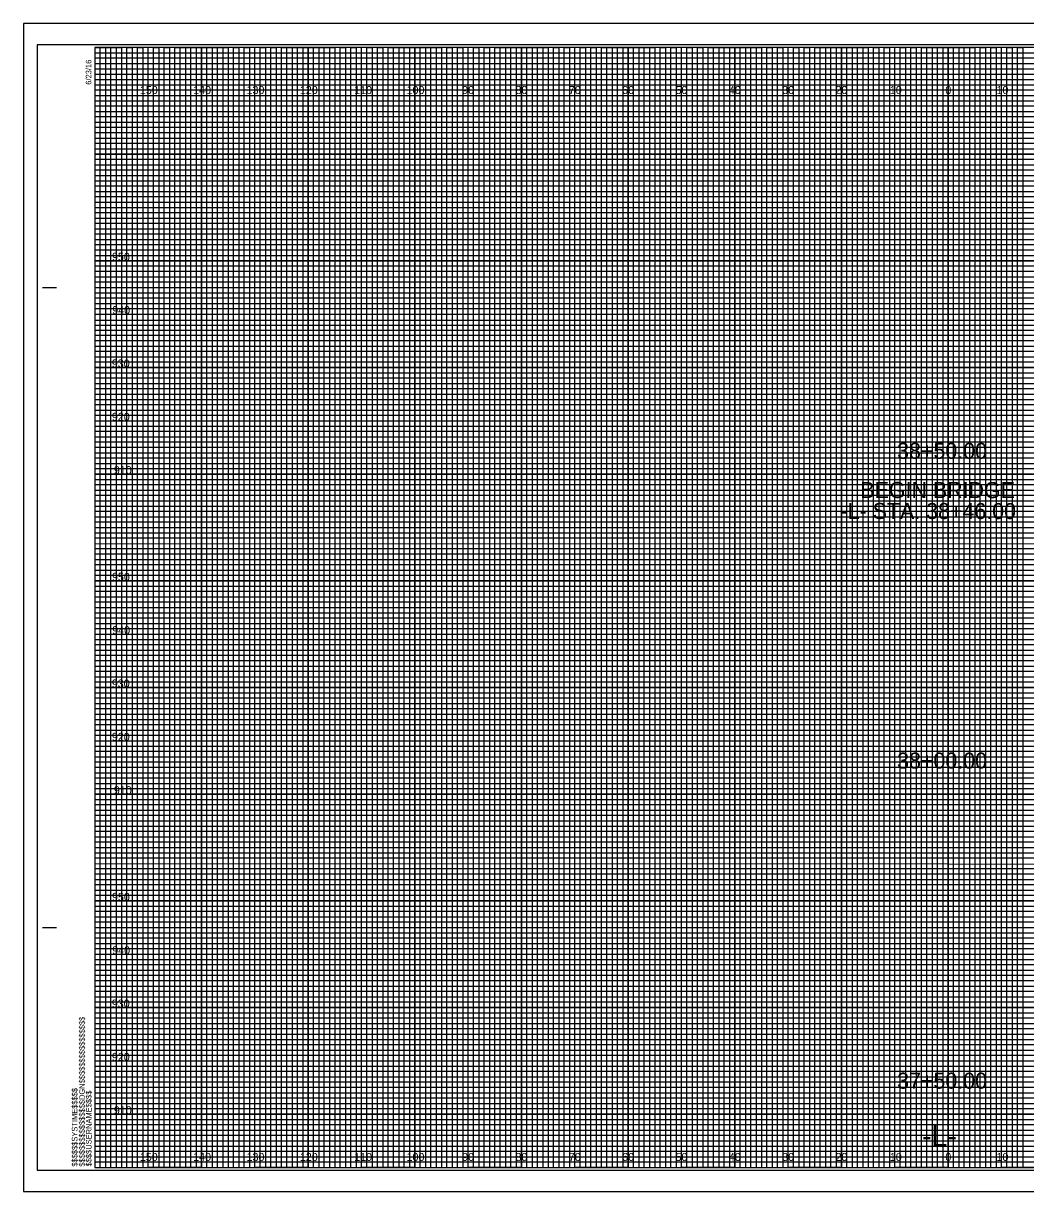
# Model space of a CAD drawing. Extents: x -13 to 323, y -4 to 3074.
# Drawn here: x -13.4 to 174.5, y 1095.5 to 1314.5 of the extents above; entities that cross this region are included whole.
import ezdxf

# ---------------------------------------------------------------- set-up
doc = ezdxf.new("R2010")
doc.units = 0
for name, color, linetype in [('Prop XS Alignment Label', 7, 'Continuous'), ('Prop XS Elevation Labels', 7, 'Continuous'), ('Prop XS Offset Labels', 7, 'Continuous'), ('Prop XS SE Text', 7, 'Continuous'), ('Prop XS Station Labels', 7, 'Continuous'), ('Sheet Cross Section CELL', 7, 'Continuous'), ('Sheet Cross Section Grid Major CELL', 7, 'Continuous'), ('Sheet Cross Section Grid Middle CELL', 7, 'Continuous'), ('Sheet Cross Section Grid Minor 1 CELL', 7, 'Continuous'), ('Sheet Cross Section Grid Minor 2 CELL', 7, 'Continuous'), ('Sheet Cutting Line CELL', 7, 'Continuous'), ('Sheet DOT Grid CELL', 7, 'Continuous'), ('Sheet Plot Border Inside CELL', 7, 'Continuous'), ('Sheet Plot Border Outside CELL', 7, 'Continuous')]:
    doc.layers.add(name, color=color, linetype=linetype)

msp = doc.modelspace()

# ---------------------------------------------------------------- linework, layer by layer
at = {"layer": 'Sheet Cross Section CELL'}
for p, q in [((-9.8, 1265), (-7.3, 1265)), ((-9.7, 1265), (-7.2, 1265)), ((-9.8, 1145), (-7.3, 1145)), ((-9.7, 1145), (-7.2, 1145)), ((0, 1100), (0, 1100)), ((0, 1100), (0, 1100)), ((0, 1100), (0, 1100)), ((0, 1100), (0, 1100)), ((0, 1100), (0, 1100)), ((0, 1100), (0, 1100)), ((0, 1100), (0, 1100))]:
    msp.add_line(p, q, dxfattribs=at)
msp.add_lwpolyline([(320, 1310), (0, 1310), (0, 1100), (320, 1100)], close=True, dxfattribs=at)
at = {"layer": 'Sheet Cross Section Grid Major CELL'}
for p, q in [((10, 1310), (0, 1310)), ((10, 1100), (10, 1310)), ((30, 1310), (20, 1310)), ((20, 1310), (20, 1100)), ((30, 1100), (30, 1310)), ((50, 1310), (40, 1310)), ((40, 1310), (40, 1100)), ((50, 1100), (50, 1310)), ((70, 1310), (60, 1310)), ((60, 1310), (60, 1100)), ((70, 1100), (70, 1310)), ((90, 1310), (80, 1310)), ((80, 1310), (80, 1100)), ((90, 1100), (90, 1310)), ((110, 1310), (100, 1310)), ((100, 1310), (100, 1100)), ((110, 1100), (110, 1310)), ((130, 1310), (120, 1310)), ((120, 1310), (120, 1100)), ((130, 1100), (130, 1310)), ((150, 1310), (140, 1310)), ((140, 1310), (140, 1100)), ((150, 1100), (150, 1310)), ((170, 1310), (160, 1310)), ((160, 1310), (160, 1100)), ((170, 1100), (170, 1310)), ((20, 1100), (10, 1100)), ((40, 1100), (30, 1100)), ((60, 1100), (50, 1100)), ((80, 1100), (70, 1100)), ((100, 1100), (90, 1100)), ((120, 1100), (110, 1100)), ((140, 1100), (130, 1100)), ((160, 1100), (150, 1100)), ((180, 1100), (170, 1100))]:
    msp.add_line(p, q, dxfattribs=at)
for points in [[(0, 1300), (320, 1300), (320, 1290), (0, 1290)], [(0, 1280), (320, 1280), (320, 1270), (0, 1270)], [(0, 1260), (320, 1260), (320, 1250), (0, 1250)], [(0, 1240), (320, 1240), (320, 1230), (0, 1230)], [(0, 1220), (320, 1220), (320, 1210), (0, 1210)], [(0, 1200), (320, 1200), (320, 1190), (0, 1190)], [(0, 1180), (320, 1180), (320, 1170), (0, 1170)], [(0, 1160), (320, 1160), (320, 1150), (0, 1150)], [(0, 1140), (320, 1140), (320, 1130), (0, 1130)], [(0, 1120), (320, 1120), (320, 1110), (0, 1110)]]:
    msp.add_lwpolyline(points, dxfattribs=at)
at = {"layer": 'Sheet Cross Section Grid Middle CELL'}
for points in [[(0, 1310), (5, 1310), (5, 1100), (15, 1100), (15, 1310), (25, 1310), (25, 1100), (35, 1100), (35, 1310), (45, 1310), (45, 1100), (55, 1100), (55, 1310), (65, 1310), (65, 1100), (75, 1100), (75, 1310), (85, 1310), (85, 1100), (95, 1100), (95, 1310), (105, 1310), (105, 1100), (115, 1100), (115, 1310), (125, 1310), (125, 1100), (135, 1100), (135, 1310), (145, 1310), (145, 1100), (155, 1100), (155, 1310), (165, 1310), (165, 1100), (175, 1100)], [(0, 1305), (275, 1305)], [(0, 1285), (320, 1285), (320, 1295), (0, 1295)], [(0, 1265), (320, 1265), (320, 1275), (0, 1275)], [(0, 1245), (320, 1245), (320, 1255), (0, 1255)], [(0, 1225), (320, 1225), (320, 1235), (0, 1235)], [(0, 1205), (320, 1205), (320, 1215), (0, 1215)], [(0, 1185), (320, 1185), (320, 1195), (0, 1195)], [(0, 1165), (320, 1165), (320, 1175), (0, 1175)], [(0, 1145), (320, 1145), (320, 1155), (0, 1155)], [(0, 1125), (320, 1125), (320, 1135), (0, 1135)], [(0, 1105), (320, 1105), (320, 1115), (0, 1115)]]:
    msp.add_lwpolyline(points, dxfattribs=at)
at = {"layer": 'Sheet Cross Section Grid Minor 1 CELL'}
for p, q in [((0, 1309), (260, 1309)), ((260, 1307.98), (0, 1307.98)), ((0, 1307.98), (0, 1307)), ((0, 1307), (260, 1307)), ((260, 1305.89), (0, 1305.89)), ((0, 1305.89), (0, 1304)), ((0, 1304), (320, 1304))]:
    msp.add_line(p, q, dxfattribs=at)
for points in [[(0, 1303), (270, 1303), (320, 1303), (320, 1302), (0, 1302)], [(0, 1301), (320, 1301), (320, 1299), (0, 1299)], [(0, 1298), (320, 1298), (320, 1297), (0, 1296.98)], [(0, 1296), (320, 1296), (320, 1294), (0, 1294)], [(0, 1293), (320, 1293), (320, 1292), (0, 1292)], [(0, 1291), (320, 1291), (320, 1289), (0, 1289)], [(0, 1288), (320, 1288), (320, 1287), (0, 1287)], [(0, 1286), (320, 1286), (320, 1284), (0, 1284)], [(0, 1283), (320, 1283), (320, 1282), (0, 1282)], [(0, 1281), (320, 1281), (320, 1279), (0, 1279)], [(0, 1278), (320, 1278), (320, 1277), (0, 1277)], [(0, 1276), (320, 1276), (320, 1273.95), (320, 1273), (320, 1272), (0, 1272)], [(0, 1274), (320, 1274), (320, 1273), (0, 1273)], [(0, 1271), (320, 1271), (320, 1269), (0, 1269.03)], [(0, 1269.03), (320, 1269), (320, 1268), (0, 1268)], [(0, 1267), (320, 1267), (320, 1266), (0, 1266)], [(0, 1264), (320, 1264), (320, 1263), (0, 1263)], [(0, 1262), (320, 1262), (320, 1261), (0, 1261)], [(-0.07, 1258.89), (320, 1258.89), (320, 1257.88), (-0.07, 1257.88)], [(0, 1257), (320, 1257), (320, 1256), (0, 1256)], [(0, 1254), (320, 1254), (320, 1253), (0, 1253)], [(0, 1252), (320, 1252), (320, 1251), (0, 1251)], [(0, 1249), (320, 1249), (320, 1248), (0, 1248)], [(0, 1247), (320, 1247), (320, 1246), (0, 1246)], [(0, 1244), (320, 1244), (320, 1243), (0, 1243)], [(0, 1242), (320, 1242), (320, 1241), (0, 1241)], [(0, 1239), (320, 1239), (319.99, 1237.98), (0, 1238)], [(0, 1237), (320, 1237), (320, 1236), (0, 1236)], [(0, 1234), (320, 1234), (320, 1233), (0, 1233)], [(0, 1232), (320, 1232), (320, 1231), (0, 1231)], [(0, 1229), (320, 1229), (320, 1228), (0, 1228)], [(0, 1227), (320, 1227), (320, 1226), (0, 1226)], [(0, 1224), (320, 1224), (320, 1223), (0, 1223)], [(0, 1222), (320, 1222), (320, 1221), (0, 1221)], [(0, 1219), (320, 1219), (320, 1218), (0, 1218)], [(0, 1216.99), (320.07, 1216.91), (320, 1216), (0, 1216)], [(0, 1214), (320, 1214), (320, 1213), (0, 1213)], [(0, 1212), (320, 1212), (320, 1211), (0, 1211)], [(0, 1209), (320, 1209), (320, 1208), (0, 1208)], [(0, 1207), (320, 1207), (320, 1206), (0, 1206)], [(0, 1204), (320, 1204), (320, 1203), (0, 1203)], [(0, 1202), (320, 1202), (320, 1201), (0, 1201)], [(0, 1199), (320, 1199), (320, 1198), (0, 1198)], [(0, 1197), (320, 1197), (320, 1196), (0, 1196)], [(0, 1194), (320, 1194), (320, 1193), (0, 1193)], [(0, 1192), (320, 1192), (320, 1191), (0, 1191)], [(0, 1189), (320, 1189), (320, 1188), (0, 1188)], [(0, 1187), (320, 1187), (320, 1186), (0, 1186)], [(0, 1184), (320, 1184), (320, 1183), (0, 1183)], [(0, 1182), (320, 1182), (320, 1181), (0, 1181)], [(0, 1179), (320, 1179), (319.99, 1177.98), (0, 1178)], [(0, 1177), (320, 1177), (320, 1176), (0, 1176)], [(0, 1174), (320, 1174), (320, 1173), (0, 1173)], [(0, 1172), (320, 1172), (320, 1171), (0, 1171)], [(0, 1169), (320, 1169), (320, 1168), (0, 1168)], [(0, 1167), (320, 1167), (320, 1166), (0, 1166)], [(0, 1164), (320, 1164), (320, 1163), (0, 1163)], [(0, 1162), (320, 1162), (320, 1161), (0, 1161)], [(0, 1159), (320, 1159), (320, 1158), (0, 1158)], [(0, 1156.99), (320.07, 1156.91), (320, 1156), (0, 1156)], [(0, 1154), (320, 1154), (320, 1153), (0, 1153)], [(0, 1152), (320, 1152), (320, 1151), (0, 1151)], [(0, 1149), (320, 1149), (320, 1148), (0, 1148)], [(0, 1147), (320, 1147), (320, 1146), (0, 1146)], [(0, 1144), (320, 1144), (320, 1143), (0, 1143)], [(0, 1142), (320, 1142), (320, 1141), (0, 1141)], [(0, 1139), (320, 1139), (320, 1138), (0, 1138)], [(0, 1137), (320, 1137), (320, 1136), (0, 1136)], [(0, 1134), (320, 1134), (320, 1133), (0, 1133)], [(0, 1132), (320, 1132), (320, 1131), (0, 1131)], [(0, 1129), (320, 1129), (320, 1128), (0, 1128)], [(0, 1127), (320, 1127), (320, 1126), (0, 1126)], [(0, 1124), (320, 1124), (320, 1123), (0, 1123)], [(0, 1122), (320, 1122), (320, 1121), (0, 1121)], [(0, 1119), (320, 1119), (320, 1118), (0, 1118)], [(0, 1117), (320, 1117), (320, 1116), (0, 1116)], [(0, 1114), (320, 1114), (320, 1113), (0, 1113)], [(0, 1112), (320, 1112), (320, 1111), (0, 1111)], [(0, 1109), (320, 1109), (320, 1108), (0, 1108)], [(0, 1107), (320, 1107), (320, 1106), (0, 1106)], [(0, 1104), (320, 1104), (320, 1103), (0, 1103)], [(0, 1102), (320, 1102), (320, 1101), (0, 1101)]]:
    msp.add_lwpolyline(points, dxfattribs=at)
at = {"layer": 'Sheet Cross Section Grid Minor 2 CELL'}
for points in [[(0, 1100), (1, 1100), (1, 1310), (2, 1310), (2, 1100)], [(2, 1100), (3, 1100), (3, 1310), (4, 1310), (4, 1100)], [(5, 1100), (6, 1100), (6, 1310), (7, 1310), (7, 1100)], [(7, 1100), (8, 1100), (8, 1310), (9, 1310), (9, 1100)], [(10, 1100), (11, 1100), (11, 1310), (12, 1310), (12, 1100)], [(12, 1100), (13, 1100), (13, 1310), (14, 1310), (14, 1100)], [(15, 1100), (16, 1100), (16, 1310), (17, 1310), (17, 1100)], [(17, 1100), (18, 1100), (18, 1310), (19, 1310), (19, 1100)], [(20, 1100), (21, 1100), (21, 1310), (22, 1310), (22, 1100)], [(22, 1100), (23, 1100), (23, 1310), (24, 1310), (24, 1100)], [(25, 1100), (26, 1100), (26, 1310), (27, 1310), (27, 1100)], [(27, 1100), (28, 1100), (28, 1310), (29, 1310), (29, 1100)], [(30, 1100), (31, 1100), (31, 1310), (32, 1310), (32, 1100)], [(32, 1100), (33, 1100), (33, 1310), (34, 1310), (34, 1100)], [(35, 1100), (36, 1100), (36, 1310), (37, 1310), (37, 1100)], [(37, 1100), (38, 1100), (38, 1310), (39, 1310), (39, 1100)], [(40, 1100), (41, 1100), (41, 1310), (42, 1310), (42, 1100)], [(42, 1100), (43, 1100), (43, 1310), (44, 1310), (44, 1100)], [(45, 1100), (46, 1100), (46, 1310), (47, 1310), (47, 1100)], [(47, 1100), (48, 1100), (48, 1310), (49, 1310), (49, 1100)], [(50, 1100), (51, 1100), (51, 1310), (52, 1310), (52, 1100)], [(52, 1100), (53, 1100), (53, 1310), (54, 1310), (54, 1100)], [(55, 1100), (56, 1100), (56, 1310), (57, 1310), (57, 1100)], [(57, 1100), (58, 1100), (58, 1310), (59, 1310), (59, 1100)], [(60, 1100), (61, 1100), (61, 1310), (62, 1310), (62, 1100)], [(62, 1100), (63, 1100), (63, 1310), (64, 1310), (64, 1100)], [(65, 1100), (66, 1100), (66, 1310), (67, 1310), (67, 1100)], [(67, 1100), (68, 1100), (68, 1310), (69, 1310), (69, 1100)], [(70, 1100), (71, 1100), (71, 1310), (72, 1310), (72, 1100)], [(72, 1100), (73, 1100), (73, 1310), (74, 1310), (74, 1100)], [(75, 1100), (76, 1100), (76, 1310), (77, 1310), (77, 1100)], [(77, 1100), (78, 1100), (78, 1310), (79, 1310), (79, 1100)], [(80, 1100), (81, 1100), (81, 1310), (82, 1310), (82, 1100)], [(82, 1100), (83, 1100), (83, 1310), (84, 1310), (84, 1100)], [(85, 1100), (86, 1100), (86, 1310), (87, 1310), (87, 1100)], [(87, 1100), (88, 1100), (88, 1310), (89, 1310), (89, 1100)], [(90, 1100), (91, 1100), (91, 1310), (92, 1310), (92, 1100)], [(92, 1100), (93, 1100), (93, 1310), (94, 1310), (94, 1100)], [(95, 1100), (96, 1100), (96, 1310), (97, 1310), (97, 1100)], [(97, 1100), (98, 1100), (98, 1310), (99, 1310), (99, 1100)], [(100, 1100), (101, 1100), (101, 1310), (102, 1310), (102, 1100)], [(102, 1100), (103, 1100), (103, 1310), (104, 1310), (104, 1100)], [(105, 1100), (106, 1100), (106, 1310), (107, 1310), (107, 1100)], [(107, 1100), (108, 1100), (108, 1310), (109, 1310), (109, 1100)], [(110, 1100), (111, 1100), (111, 1310), (112, 1310), (112, 1100)], [(112, 1100), (113, 1100), (113, 1310), (114, 1310), (114, 1100)], [(115, 1100), (116, 1100), (116, 1310), (117, 1310), (117, 1100)], [(117, 1100), (118, 1100), (118, 1310), (119, 1310), (119, 1100)], [(120, 1100), (121, 1100), (121, 1310), (122, 1310), (122, 1100)], [(122, 1100), (123, 1100), (123, 1310), (124, 1310), (124, 1100)], [(125, 1100), (126, 1100), (126, 1310), (127, 1310), (127, 1100)], [(127, 1100), (128, 1100), (128, 1310), (129, 1310), (129, 1100)], [(130, 1100), (131, 1100), (131, 1310), (132, 1310), (132, 1100)], [(132, 1100), (133, 1100), (133, 1310), (134, 1310), (134, 1100)], [(135, 1100), (136, 1100), (136, 1310), (137, 1310), (137, 1100)], [(137, 1100), (138, 1100), (138, 1310), (139, 1310), (139, 1100)], [(140, 1100), (141, 1100), (141, 1310), (142, 1310), (142, 1100)], [(142, 1100), (143, 1100), (143, 1310), (144, 1310), (144, 1100)], [(145, 1100), (146, 1100), (146, 1310), (147, 1310), (147, 1100)], [(147, 1100), (148, 1100), (148, 1310), (149, 1310), (149, 1100)], [(150, 1100), (151, 1100), (151, 1310), (152, 1310), (152, 1100)], [(152, 1100), (153, 1100), (153, 1310), (154, 1310), (154, 1100)], [(155, 1100), (156, 1100), (156, 1310), (157, 1310), (157, 1100)], [(157, 1100), (158, 1100), (158, 1310), (159, 1310), (159, 1100)], [(160, 1100), (161, 1100), (161, 1310), (162, 1310), (162, 1100)], [(162, 1100), (163, 1100), (163, 1310), (164, 1310), (164, 1100)], [(165, 1100), (166, 1100), (166, 1310), (167, 1310), (167, 1100)], [(167, 1100), (168, 1100), (168, 1310), (169, 1310), (169, 1100)], [(170, 1100), (171, 1100), (171, 1310), (172, 1310), (172, 1100)], [(172, 1100), (173, 1100), (173, 1310), (174, 1310), (174, 1100)]]:
    msp.add_lwpolyline(points, dxfattribs=at)
at = {"layer": 'Sheet Cutting Line CELL'}
for p, q in [((323.3, 1314.5), (-13.4, 1314.5)), ((-13.4, 1314.5), (-13.4, 1095.5)), ((-13.4, 1095.5), (323.3, 1095.5))]:
    msp.add_line(p, q, dxfattribs=at)
at = {"layer": 'Sheet DOT Grid CELL'}
for p, q in [((10, 1100), (10, 1310)), ((20, 1100), (20, 1310)), ((30, 1100), (30, 1310)), ((40, 1100), (40, 1310)), ((50, 1100), (50, 1310)), ((60, 1100), (60, 1310)), ((70, 1100), (70, 1310)), ((80, 1100), (80, 1310)), ((90, 1100), (90, 1310)), ((100, 1100), (100, 1310)), ((110, 1100), (110, 1310)), ((120, 1100), (120, 1310)), ((130, 1100), (130, 1310)), ((140, 1100), (140, 1310)), ((150, 1100), (150, 1310)), ((160, 1100), (160, 1310)), ((170, 1100), (170, 1310)), ((0, 1300), (320, 1300)), ((0, 1290), (320, 1290)), ((0, 1280), (320, 1280)), ((0, 1270), (320, 1270)), ((0, 1260), (320, 1260)), ((0, 1250), (320, 1250)), ((0, 1240), (320, 1240)), ((0, 1230), (320, 1230)), ((0, 1220), (320, 1220)), ((0, 1210), (320, 1210)), ((0, 1200), (320, 1200)), ((0, 1190), (320, 1190)), ((0, 1180), (320, 1180)), ((0, 1170), (320, 1170)), ((0, 1160), (320, 1160)), ((0, 1150), (320, 1150)), ((0, 1140), (320, 1140)), ((0, 1130), (320, 1130)), ((0, 1120), (320, 1120)), ((0, 1110), (320, 1110))]:
    msp.add_line(p, q, dxfattribs=at)
at = {"layer": 'Sheet Plot Border Inside CELL'}
msp.add_lwpolyline([(-10.8, 1099.5), (322.4, 1099.5), (322.4, 1310.5), (-10.8, 1310.5)], close=True, dxfattribs=at)
at = {"layer": 'Sheet Plot Border Outside CELL'}
msp.add_lwpolyline([(-13.4, 1095.5), (323.3, 1095.5), (323.3, 1314.5), (-13.4, 1314.5)], close=True, dxfattribs=at)

# ---------------------------------------------------------------- texts
at = {"layer": 'Prop XS Alignment Label'}
msp.add_text('-L-', height=4, dxfattribs=at).set_placement((155.06, 1104))
at = {"layer": 'Prop XS Elevation Labels'}
for s, p in [('950', (3.22, 1270)), ('940', (3.26, 1260)), ('930', (3.18, 1250)), ('920', (3.19, 1240)), ('910', (3.57, 1230)), ('950', (3.22, 1210)), ('940', (3.26, 1200)), ('930', (3.18, 1190)), ('920', (3.19, 1180)), ('910', (3.57, 1170)), ('950', (3.22, 1150)), ('940', (3.26, 1140)), ('930', (3.18, 1130)), ('920', (3.19, 1120)), ('910', (3.57, 1110))]:
    msp.add_text(s, height=1.5, dxfattribs=at).set_placement(p)
at = {"layer": 'Prop XS Offset Labels'}
for s, p in [('150', (8.44, 1301.25)), ('140', (18.44, 1301.25)), ('130', (28.44, 1301.25)), ('120', (38.44, 1301.25)), ('110', (48.62, 1301.25)), ('100', (58.44, 1301.25)), ('90', (68.86, 1301.25)), ('80', (78.86, 1301.25)), ('70', (88.86, 1301.25)), ('60', (98.86, 1301.25)), ('50', (108.86, 1301.25)), ('40', (118.86, 1301.25)), ('30', (128.86, 1301.25)), ('20', (138.86, 1301.25)), ('10', (149.04, 1301.25)), ('0', (159.45, 1301.25)), ('0', (159.45, 1301.25)), ('10', (169.04, 1301.25)), ('150', (8.44, 1101.25)), ('140', (18.44, 1101.25)), ('130', (28.44, 1101.25)), ('120', (38.44, 1101.25)), ('110', (48.62, 1101.25)), ('100', (58.44, 1101.25)), ('90', (68.86, 1101.25)), ('80', (78.86, 1101.25)), ('70', (88.86, 1101.25)), ('60', (98.86, 1101.25)), ('50', (108.86, 1101.25)), ('40', (118.86, 1101.25)), ('30', (128.86, 1101.25)), ('20', (138.86, 1101.25)), ('10', (149.04, 1101.25)), ('0', (159.45, 1101.25)), ('0', (159.45, 1101.25)), ('10', (169.04, 1101.25))]:
    msp.add_text(s, height=1.5, dxfattribs=at).set_placement(p)
at = {"layer": 'Prop XS SE Text'}
for s, p in [('BEGIN BRIDGE', (143.51, 1225.53)), ('-L- STA. 38+46.00', (139.8, 1221.6))]:
    msp.add_text(s, height=3, rotation=359.9573, dxfattribs=at).set_placement(p)
at = {"layer": 'Prop XS Station Labels'}
for s, p in [('38+50.00', (150.41, 1232.87)), ('38+00.00', (150.41, 1174.8)), ('37+50.00', (150.41, 1114.8))]:
    msp.add_text(s, height=3, dxfattribs=at).set_placement(p)
at = {"layer": 'Sheet Cross Section CELL'}
for s, p in [('6/23/16', (-0.65, 1303)), ('$$$$$$$$$$$$$$$$DGN$$$$$$$$$$$$$$$$', (-1.88, 1100.18)), ('$$$$$$SYSTIME$$$$$', (-3.26, 1100.18)), ('$$$$USERNAME$$$$', (-0.62, 1100.23))]:
    msp.add_text(s, height=1.05, rotation=90, dxfattribs=at).set_placement(p)

doc.saveas('drawing.dxf')
